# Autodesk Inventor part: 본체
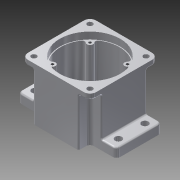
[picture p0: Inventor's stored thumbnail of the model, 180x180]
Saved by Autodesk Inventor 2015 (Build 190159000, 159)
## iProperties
Created: 2014-12
Part Number: 본체
Material: 알루미늄 6061
Document SubType Name: Modeling
Designer: bom
Density: 2.7 g/cm^3
Appearance: 알루미늄 - 평지
Mass: 702.348 g
Surface Area: 671.426 cm^2
Volume: 260.129 cm^3
Author: bom
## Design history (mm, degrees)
sketch "스케치1"
  geometry: L1 (-60, 30)-(-35, 30); L2 (-30, 35)-(-30, 45); L3 (-30, 45)-(30, 45); L4 (30, 45)-(30, 35); L5 (35, 30)-(60, 30); L6 (65, 25)-(65, -25); L7 (60, -30)-(35, -30); L8 (30, -35)-(30, -45); L9 (30, -45)-(-30, -45); L10 (-30, -45)-(-30, -35); L11 (-35, -30)-(-60, -30); L12 (-65, -25)-(-65, 25); C1 r 4.5 at (-54.123, 20.114); C2 r 4.5 at (-54.123, -14.886); C3 r 4.5 at (55.877, 20.114); C4 r 4.5 at (55.877, -14.886); A1 r 5 centre (-35, 35) between (-35, 30) and (-30, 35); A2 r 5 centre (35, 35) between (30, 35) and (35, 30); A3 r 5 centre (35, -35) between (35, -30) and (30, -35); A4 r 5 centre (-35, -35) between (-30, -35) and (-35, -30); A5 r 5 centre (-60, 25) between (-60, 30) and (-65, 25); A6 r 5 centre (-60, -25) between (-65, -25) and (-60, -30); A7 r 5 centre (60, -25) between (60, -30) and (65, -25); A8 r 5 centre (60, 25) between (65, 25) and (60, 30); 7 further points
  constraints: 24 end point, 16 point on circle, 16 tangent, 12 centre point, 10 equal radius, 8 perpendicular, 8 point on line, 4 vertical alignment, 3 horizontal alignment, 3 midpoint, 3 parallel, 2 horizontal
  dimensions: "d0" = 60 distance of L2.end L3.end; "d1" = 60 distance of point (-65, -30) point (-65, 30); "d2" = 130 distance between parallel lines of L6 L12; "d3" = 65 distance of point (0, 0) point (-65, 0); "d4" = 90 distance between parallel lines of L9 L3; "d5" = 45 distance of point (0, 45) point (0, 0); "d6" = 5 radius of A1; "d9" = 9 diameter of C1; "d10" = 110 distance of C3.centre C1.centre; "d11" = 35 distance of C2.centre C1.centre
extrude "돌출1" new body sketch "스케치1" distance "d7" = 12; taper "d8" = 0 deg
sketch "스케치25"
  geometry: C1 r 4.5 at (55, -17.5); C2 r 4.5 at (55, 17.5); C3 r 4.5 at (-55, -17.5); C4 r 4.5 at (-55, 17.5); 1 further point
  constraints: 4 centre point, 3 equal radius, 2 horizontal alignment, 2 vertical alignment
  dimensions: "d117" = 9 diameter of C1; "d118" = 110 distance of C3.centre C1.centre; "d119" = 55 horizontal distance of point (0, 0) C1.centre; "d120" = 35 distance of C2.centre C1.centre; "d121" = 17.5 vertical distance of point (0, 0) C2.centre
extrude "돌출16" cut sketch "스케치25" stored distance "d122" = 10; taper "d123" = 0 deg
sketch "스케치4"
  geometry: L1 (30, 45)-(-30, 45) reference; L2 (-30, 45)-(-30, 35) reference; L3 (-35, 30)-(-60, 30) reference; L4 (30, 35)-(30, 45) reference; L5 (60, 30)-(35, 30) reference; L6 (35, -30)-(60, -30) reference; L7 (30, -45)-(30, -35) reference; L8 (-30, -45)-(30, -45) reference; L9 (-30, -35)-(-30, -45) reference; L10 (-60, -30)-(-35, -30) reference; L11 (-45, 30)-(-45, -30); L12 (45, 30)-(45, -30); A1 r 5 centre (-35, 35) between (-35, 30) and (-30, 35) reference; A2 r 5 centre (35, 35) between (30, 35) and (35, 30) reference; A3 r 5 centre (35, -35) between (35, -30) and (30, -35) reference; A4 r 5 centre (-35, -35) between (-30, -35) and (-35, -30) reference; 1 further point
  constraints: 4 end point, 4 point on line, 2 vertical
  dimensions: "d23" = 90 distance between parallel lines of L12 L11; "d24" = 45 distance from line of L11 point (0, 0)
extrude "돌출2" join sketch "스케치4" distance "d25" = 58; taper "d26" = 0 deg
sketch "스케치6"
  geometry: L1 (30, 45)-(-30, 45) reference; L2 (-45, 30)-(-45, -30) reference; L3 (-30, -45)-(30, -45) reference; L4 (45, -30)-(45, 30) reference; L5 (37, -45)-(-37, -45); L6 (-45, -37)-(-45, 37); L7 (-37, 45)-(37, 45); L8 (45, 37)-(45, -37); L9 (45, -45)-(-45, 45); L10 (-45, -45)-(45, 45); C1 r 3.5 at (-37, 37); C2 r 3.5 at (37, 37); C3 r 3.5 at (37, -37); C4 r 3.5 at (-37, -37); A1 r 8 centre (-37, 37) between (-37, 45) and (-45, 37); A2 r 8 centre (37, 37) between (45, 37) and (37, 45); A3 r 8 centre (37, -37) between (37, -45) and (45, -37); A4 r 8 centre (-37, -37) between (-45, -37) and (-37, -45); 1 further point
  constraints: 12 end point, 8 centre point, 8 point on circle, 8 point on line, 8 tangent, 6 equal radius, 4 coincident, 2 midpoint, 2 parallel, 1 horizontal, 1 perpendicular
  dimensions: "d27" = 90 distance of L9.end L10.end; "d28" = 90 distance of L10.start L9.end; "d29" = 8 radius of A1; "d30" = 7 diameter of C1
extrude "돌출3" join sketch "스케치6" distance "d31" = 7; taper "d32" = 0 deg
sketch "스케치7"
  geometry: C1 r 40 at (0, 0); 1 further point
  constraints: 1 centre point, 1 coincident
  dimensions: "d33" = 80 diameter of C1
extrude "돌출4" cut sketch "스케치7" distance "d34" = 9; taper "d35" = 0 deg
sketch "스케치8"
  geometry: C1 r 39 at (0, 0); 1 further point
  constraints: 1 centre point, 1 coincident
  dimensions: "d36" = 78 diameter of C1
extrude "돌출5" cut sketch "스케치8" distance "d37" = 52; taper "d38" = 0 deg
sketch "스케치9"
  geometry: C1 r 25 at (0, 11); 1 further point
  constraints: 1 centre point, 1 vertical alignment
  dimensions: "d39" = 50 diameter of C1; "d40" = 11 distance of point (0, 0) C1.centre
extrude "돌출6" join sketch "스케치9" distance "d41" = 7; taper "d42" = 0 deg
sketch "스케치13"
  geometry: A1 r 14 centre (0, -20) between (-10.493, -10.732) and (10.493, -10.732); A2 r 20.5 centre (0, 11) between (11.115, -6.225) and (-11.115, -6.225); A3 r 3 centre (-12.742, -8.746) between (-10.493, -10.732) and (-11.115, -6.225); A4 r 3 centre (12.742, -8.746) between (11.115, -6.225) and (10.493, -10.732); 1 further point
  constraints: 8 point on circle, 4 centre point, 4 tangent, 2 vertical alignment
  dimensions: "d46" = 28 diameter of A1; "d47" = 20 distance of point (0, 0) A1.centre; "d49" = 41 diameter of A2; "d50" = 11 distance of point (0, 0) A2.centre; "d51" = 3 radius of A3; "d52" = 3 radius of A4
extrude "돌출8" join sketch "스케치13" distance "d53" = 7; taper "d54" = 0 deg
sketch "스케치14"
  geometry: C1 r 17.5 at (0, 11); A1 r 20.5 centre (0, 11) between (11.115, -6.225) and (-11.115, -6.225) reference; A2 r 14 centre (0, -20) between (-10.493, -10.732) and (10.493, -10.732) reference; 1 further point
  constraints: 1 centre point, 1 coincident
  dimensions: "d55" = 35 diameter of C1
extrude "돌출9" cut sketch "스케치14" distance "d56" = 10; taper "d57" = 0 deg
sketch "스케치15"
  geometry: C1 r 12.5 at (0, 0); C2 r 17.5 at (0, 0) reference; 1 further point
  constraints: 1 centre point, 1 concentric
  dimensions: "d58" = 25 diameter of C1
extrude "돌출10" cut sketch "스케치15" distance "d59" = 5; taper "d60" = 0 deg
sketch "스케치16"
  geometry: L1 (-60, 19)-(-35, 19) reference; L2 (-30, 24)-(-30, 34) reference; L3 (-30, 34)-(30, 34) reference; L4 (30, 34)-(30, 24) reference; L5 (35, 19)-(60, 19) reference; L6 (65, 14)-(65, -36) reference; L7 (60, -41)-(35, -41) reference; L8 (30, -46)-(30, -56) reference; L9 (30, -56)-(-30, -56) reference; L10 (-30, -56)-(-30, -46) reference; L11 (-35, -41)-(-60, -41) reference; L12 (-65, -36)-(-65, 14) reference; C1 r 12.5 at (0, 0) reference; C2 r 16 at (0, 0); C3 r 4.5 at (55, -28.5) reference; C4 r 4.5 at (-55, -28.5) reference; C5 r 4.5 at (-55, 6.5) reference; C6 r 4.5 at (55, 6.5) reference; A1 r 5 centre (-35, 24) between (-35, 19) and (-30, 24) reference; A2 r 5 centre (35, 24) between (30, 24) and (35, 19) reference; A3 r 5 centre (60, 14) between (65, 14) and (60, 19) reference; A4 r 5 centre (60, -36) between (60, -41) and (65, -36) reference; A5 r 5 centre (35, -46) between (35, -41) and (30, -46) reference; A6 r 5 centre (-35, -46) between (-30, -46) and (-35, -41) reference; A7 r 5 centre (-60, -36) between (-65, -36) and (-60, -41) reference; A8 r 5 centre (-60, 14) between (-60, 19) and (-65, 14) reference; 1 further point
  constraints: 1 centre point, 1 coincident
  dimensions: "d61" = 32 diameter of C2
extrude "돌출11" cut sketch "스케치16" distance "d62" = 8; taper "d63" = 0 deg
sketch "스케치17"
  geometry: C1 r 17.5 at (0, 11) reference; C2 r 11 at (0, -20); A1 r 20.5 centre (0, 11) between (11.115, -6.225) and (-11.115, -6.225) reference; A2 r 3 centre (-12.742, -8.746) between (-10.493, -10.732) and (-11.115, -6.225) reference; A3 r 14 centre (0, -20) between (-10.493, -10.732) and (10.493, -10.732) reference; A4 r 3 centre (12.742, -8.746) between (11.115, -6.225) and (10.493, -10.732) reference; 1 further point
  constraints: 1 centre point, 1 coincident
  dimensions: "d64" = 22 diameter of C2
extrude "돌출12" cut sketch "스케치17" distance "d65" = 7; taper "d66" = 0 deg
sketch "스케치18"
  geometry: C1 r 9.5 at (0, 0); C2 r 11 at (0, 0) reference; 1 further point
  constraints: 1 centre point, 1 concentric
  dimensions: "d67" = 19 diameter of C1
extrude "돌출13" cut sketch "스케치18" distance "d68" = 1; taper "d69" = 0 deg
sketch "스케치21" dims "d80" = 70
  geometry: L1 (0, 0)-(76.122, 0); L2 (0, 0)-(24.749, 24.749); A1 r 39 centre (0, 0) between (21.134, 32.777) and (32.777, 21.134) reference; A2 r 4 centre (24.749, 24.749) between (21.809, 27.462) and (27.462, 21.809); A3 r 3.5 centre (19.238, 29.836) between (21.809, 27.462) and (21.134, 32.777); A4 r 3.5 centre (29.836, 19.238) between (32.777, 21.134) and (27.462, 21.809); 1 further point
  constraints: 8 point on circle, 4 end point, 4 tangent, 3 centre point, 1 coincident, 1 horizontal, 3 other
  dimensions: "d78" = 8 diameter of A2; "d82" = 3.5 radius of A3; "d83" = 3.5 radius of A4; "d84" = 45 deg angle of L1 L2
extrude "돌출15" join sketch "스케치21" stored distance "d85" = 1; taper "d86" = 0 deg
sketch "스케치22"
  geometry: A1 r 4 centre (24.749, 24.749) between (21.809, 27.462) and (27.462, 21.809) reference; 2 further points
  constraints: 1 coincident
hole "구멍2" sketch "스케치22" at (24.749, 24.749) diameter "d87" = 3.459; stored, may be unused: countersink angle "d91" = 90 deg, drill point angle "d93" = 118 deg; dims "d88" = 12, "d89" = 4, "d90" = 2, "d92" = 15
chamfer "모따기1" distance "d97" = 1; stored, may be unused: second distance "d98" = 2, angle "d99" = 45 deg
fillet "모깎기1" dims "d100" = 0.3
chamfer "모따기2" distance "d101" = 1; stored, may be unused: second distance "d102" = 2, angle "d103" = 45 deg
fillet "모깎기2" dims "d104" = 2
fillet "모깎기3" dims "d105" = 2
fillet "모깎기4" dims "d106" = 2
fillet "모깎기5" dims "d107" = 2
fillet "모깎기6" dims "d108" = 2
fillet "모깎기7" dims "d109" = 2
fillet "모깎기8" dims "d110" = 2
fillet "모깎기9" dims "d111" = 2
sketch "스케치23"
  geometry: L1 (28, -45)-(-28, -45) reference; 2 further points
  constraints: 1 vertical alignment, 1 other
  dimensions: "d112" = 15 distance from line of L1 point (0, -30)
feature "엠보싱1" sketch "스케치23" dims "d0" = 60, "d1" = 60, "d2" = 130, "d3" = 65, "d4" = 90, "d5" = 45, "d6" = 5, "d113" = 0.5, "d114" = 0
sketch "스케치24"
  geometry: 1 further point
sketch "스케치26"
  geometry: 1 further point
node "솔리드1"
pattern_circular "원형 패턴1" dims angle "d95" = 360 deg
node "투영된 루프2"
node "절단 모서리 투영1"
other parameters: "d81" = 45 deg
